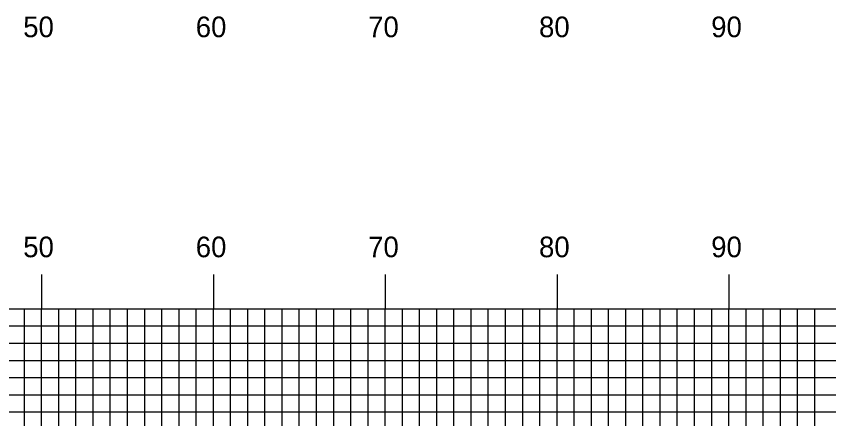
# Model space of a CAD drawing. Extents: x 1785795 to 1786139, y 442591 to 442811.
# Drawn here: x 1786009.58 to 1786056.87, y 442712.27 to 442735.68 of the extents above; entities that cross this region are included whole.
import ezdxf

# ---------------------------------------------------------------- set-up
doc = ezdxf.new("R2010")
doc.units = 0
for name, color, linetype in [('H_V ANNOTATION', 7, 'Continuous'), ('MAJOR', 7, 'Continuous'), ('MINOR', 7, 'Continuous')]:
    doc.layers.add(name, color=color, linetype=linetype)

msp = doc.modelspace()

# ---------------------------------------------------------------- linework, layer by layer
at = {"layer": 'MAJOR'}
for p, q in [((1786011.052, 442720.669), (1786011.052, 442718.665)), ((1786021.052, 442720.669), (1786021.052, 442718.665)), ((1786031.052, 442720.669), (1786031.052, 442718.665)), ((1786041.052, 442720.669), (1786041.052, 442718.665)), ((1786051.052, 442720.669), (1786051.052, 442718.665)), ((1785821.052, 442718.665), (1786101.052, 442718.665)), ((1785821.052, 442718.665), (1786101.052, 442718.665)), ((1786011.052, 442673.665), (1786011.052, 442718.665)), ((1786021.052, 442673.665), (1786021.052, 442718.665)), ((1786031.052, 442673.665), (1786031.052, 442718.665)), ((1786041.052, 442673.665), (1786041.052, 442718.665)), ((1786051.052, 442673.665), (1786051.052, 442718.665)), ((1785821.052, 442713.665), (1786101.052, 442713.665))]:
    msp.add_line(p, q, dxfattribs=at)
at = {"layer": 'MINOR'}
for p, q in [((1786010.052, 442673.665), (1786010.052, 442718.665)), ((1786012.052, 442673.665), (1786012.052, 442718.665)), ((1786013.052, 442673.665), (1786013.052, 442718.665)), ((1786014.052, 442673.665), (1786014.052, 442718.665)), ((1786015.052, 442673.665), (1786015.052, 442718.665)), ((1786016.052, 442673.665), (1786016.052, 442718.665)), ((1786017.052, 442673.665), (1786017.052, 442718.665)), ((1786018.052, 442673.665), (1786018.052, 442718.665)), ((1786019.052, 442673.665), (1786019.052, 442718.665)), ((1786020.052, 442673.665), (1786020.052, 442718.665)), ((1786022.052, 442673.665), (1786022.052, 442718.665)), ((1786023.052, 442673.665), (1786023.052, 442718.665)), ((1786024.052, 442673.665), (1786024.052, 442718.665)), ((1786025.052, 442673.665), (1786025.052, 442718.665)), ((1786026.052, 442673.665), (1786026.052, 442718.665)), ((1786027.052, 442673.665), (1786027.052, 442718.665)), ((1786028.052, 442673.665), (1786028.052, 442718.665)), ((1786029.052, 442673.665), (1786029.052, 442718.665)), ((1786030.052, 442673.665), (1786030.052, 442718.665)), ((1786032.052, 442673.665), (1786032.052, 442718.665)), ((1786033.052, 442673.665), (1786033.052, 442718.665)), ((1786034.052, 442673.665), (1786034.052, 442718.665)), ((1786035.052, 442673.665), (1786035.052, 442718.665)), ((1786036.052, 442673.665), (1786036.052, 442718.665)), ((1786037.052, 442673.665), (1786037.052, 442718.665)), ((1786038.052, 442673.665), (1786038.052, 442718.665)), ((1786039.052, 442673.665), (1786039.052, 442718.665)), ((1786040.052, 442673.665), (1786040.052, 442718.665)), ((1786042.052, 442673.665), (1786042.052, 442718.665)), ((1786043.052, 442673.665), (1786043.052, 442718.665)), ((1786044.052, 442673.665), (1786044.052, 442718.665)), ((1786045.052, 442673.665), (1786045.052, 442718.665)), ((1786046.052, 442673.665), (1786046.052, 442718.665)), ((1786047.052, 442673.665), (1786047.052, 442718.665)), ((1786048.052, 442673.665), (1786048.052, 442718.665)), ((1786049.052, 442673.665), (1786049.052, 442718.665)), ((1786050.052, 442673.665), (1786050.052, 442718.665)), ((1786052.052, 442673.665), (1786052.052, 442718.665)), ((1786053.052, 442673.665), (1786053.052, 442718.665)), ((1786054.052, 442673.665), (1786054.052, 442718.665)), ((1786055.052, 442673.665), (1786055.052, 442718.665)), ((1786056.052, 442673.665), (1786056.052, 442718.665)), ((1785821.052, 442717.665), (1786101.052, 442717.665)), ((1785821.052, 442716.665), (1786101.052, 442716.665)), ((1785821.052, 442715.665), (1786101.052, 442715.665)), ((1785821.052, 442714.665), (1786101.052, 442714.665)), ((1785821.052, 442712.665), (1786101.052, 442712.665))]:
    msp.add_line(p, q, dxfattribs=at)

# ---------------------------------------------------------------- texts
at = {"layer": 'H_V ANNOTATION'}
for s, p in [('50', (1786009.981, 442734.465)), ('60', (1786020.024, 442734.465)), ('70', (1786030.056, 442734.465)), ('80', (1786040.003, 442734.465)), ('90', (1786050.024, 442734.465)), ('50', (1786009.981, 442721.665)), ('60', (1786020.024, 442721.665)), ('70', (1786030.056, 442721.665)), ('80', (1786040.003, 442721.665)), ('90', (1786050.024, 442721.665))]:
    msp.add_text(s, height=1.2, dxfattribs=at).set_placement(p)

doc.saveas('drawing.dxf')
